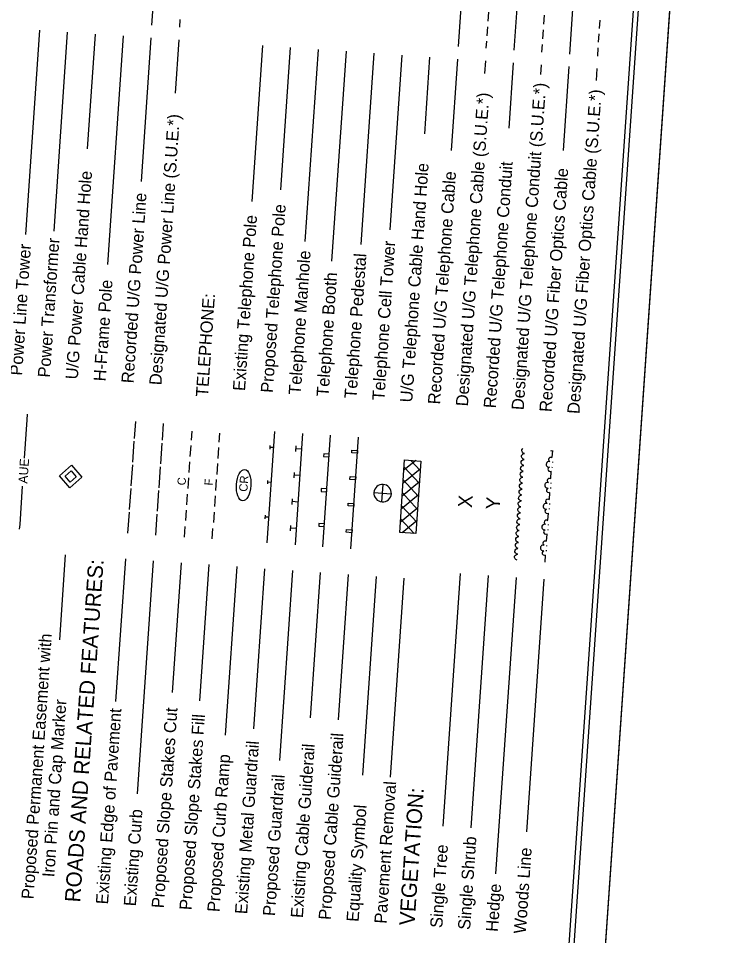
# Model space of a CAD drawing. Extents: x 2598107 to 2605763, y 726018 to 731166.
# Drawn here: x 2604643 to 2605763, y 728143 to 729620 of the extents above; entities that cross this region are included whole.
import ezdxf

# ---------------------------------------------------------------- set-up
doc = ezdxf.new("R2010")
doc.units = 0
for name, color, linetype in [('Prop ROW Permanent Easement CELL', 7, 'Continuous'), ('Prop WCC CELL', 7, 'Continuous'), ('Sheet Cutting Line CELL', 7, 'Continuous'), ('Sheet Plot Border Inside CELL', 7, 'Continuous'), ('Sheet Plot Border Outside CELL', 7, 'Continuous'), ('Sheet Symbology CELL', 7, 'Continuous')]:
    doc.layers.add(name, color=color, linetype=linetype)

msp = doc.modelspace()

# ---------------------------------------------------------------- linework, layer by layer
at = {"layer": 'Prop ROW Permanent Easement CELL'}
msp.add_line((2604727.3, 728882.4), (2604727.3, 728882.4), dxfattribs=at)
for points in [[(2604709.2, 728883.6), (2604728.5, 728900.4), (2604745.3, 728881.1), (2604726, 728864.3)], [(2604718.2, 728883), (2604727.9, 728891.4), (2604736.3, 728881.7), (2604726.6, 728873.3)]]:
    msp.add_lwpolyline(points, close=True, dxfattribs=at)
at = {"layer": 'Prop WCC CELL'}
msp.add_ellipse((2605006, 728868.4), major_axis=(1.7, 25.2), ratio=0.462467, dxfattribs=at)
at = {"layer": 'Sheet Cutting Line CELL'}
msp.add_line((2605502.8, 726876.6), (2605763.1, 730656.7), dxfattribs=at)
at = {"layer": 'Sheet Plot Border Inside CELL'}
msp.add_lwpolyline([(2605454.4, 726909.3), (2605712, 730650.1), (2603343.7, 730813.2), (2603086, 727072.4)], close=True, dxfattribs=at)
at = {"layer": 'Sheet Plot Border Outside CELL'}
msp.add_lwpolyline([(2605502.8, 726876.6), (2605763.1, 730656.7), (2603294, 730826.7), (2603033.6, 727046.7)], close=True, dxfattribs=at)
at = {"layer": 'Sheet Symbology CELL'}
for p, q in [((2604858, 729609), (2604863.9, 729694.5)), ((2605351.8, 729575), (2605357.6, 729658.3)), ((2605441.6, 729568.8), (2605447.4, 729652)), ((2605531.4, 729562.6), (2605537, 729643.1)), ((2605399.8, 729615.7), (2605400.8, 729630.3)), ((2604902.9, 729605.9), (2604903.8, 729618.2)), ((2605489.6, 729610.8), (2605490.6, 729625.4)), ((2605579.4, 729604), (2605580.3, 729617.5)), ((2604677.1, 729601.1), (2604654.4, 729272.3)), ((2604721.9, 729598), (2604699.9, 729277.3)), ((2605398.1, 729592.1), (2605399.1, 729606.7)), ((2605488, 729587.2), (2605489, 729601.8)), ((2604766.8, 729594.9), (2604754.1, 729410.1)), ((2604811.7, 729591.8), (2604786.4, 729223.9)), ((2604856.6, 729588.7), (2604840.7, 729357.6)), ((2604901.5, 729585.7), (2604895.6, 729499.9)), ((2605396.7, 729571.9), (2605397.5, 729583.2)), ((2605577.8, 729581.6), (2605578.8, 729595.1)), ((2605036.2, 729576.4), (2605018.9, 729325.2)), ((2605081.1, 729573.3), (2605065.3, 729344.2)), ((2605126, 729570.2), (2605104.7, 729260.7)), ((2605486.5, 729565.7), (2605487.4, 729578.2)), ((2605576.3, 729559.5), (2605577.2, 729572.6)), ((2605170.9, 729567.1), (2605147.6, 729229.3)), ((2605215.8, 729564), (2605194.6, 729256.1)), ((2605260.7, 729560.9), (2605241.3, 729279.8)), ((2605305.6, 729557.8), (2605297.1, 729434.3)), ((2605350.5, 729554.7), (2605340.3, 729407.6)), ((2605395.3, 729551.6), (2605393.9, 729531.1)), ((2605440.2, 729548.6), (2605433, 729443.2)), ((2605485.1, 729545.5), (2605484, 729529.6)), ((2605530, 729542.4), (2605520.8, 729407.6)), ((2605574.9, 729539.3), (2605573.6, 729520.1)), ((2604657.3, 728973.4), (2604657.9, 728982.7)), ((2604653, 728911.6), (2604657.3, 728973.4)), ((2604830.1, 728943.7), (2604832, 728970.7)), ((2604875, 728940.6), (2604876.9, 728967.6)), ((2604922.2, 728955.1), (2604921.2, 728940.7)), ((2604967.1, 728952), (2604966.1, 728937.6)), ((2605043.8, 728775.3), (2605056.2, 728954.9)), ((2605101, 728951.8), (2605088.7, 728772.2)), ((2605133.6, 728769.1), (2605145.9, 728948.7)), ((2604827.5, 728905.6), (2604829.8, 728939.3)), ((2604872.4, 728902.5), (2604874.7, 728936.2)), ((2605178.5, 728766), (2605190.8, 728945.6)), ((2604920.6, 728932), (2604919.4, 728914.4)), ((2604965.5, 728928.9), (2604964.3, 728911.3)), ((2605048.6, 728926.4), (2605048.9, 728932)), ((2605054.4, 728928.8), (2605048.7, 728929.2)), ((2605090.1, 728922.6), (2605090.7, 728931.6)), ((2605099.3, 728926.5), (2605090.4, 728927.1)), ((2605454.2, 728923.4), (2605454.3, 728925.5)), ((2605455.1, 728921.5), (2605454.2, 728923.4)), ((2605454.3, 728925.5), (2605455.6, 728927.3)), ((2605454.9, 728917.7), (2605456.5, 728918.9)), ((2605456.4, 728920.1), (2605455.1, 728921.5)), ((2605455.6, 728927.3), (2605455.7, 728927.4)), ((2605458.5, 728919.3), (2605456.4, 728920.1)), ((2605456.5, 728918.9), (2605458.4, 728919.2)), ((2605503.2, 728912.8), (2605504, 728924)), ((2604918.8, 728906.1), (2604917.6, 728888.7)), ((2605257.3, 728792.1), (2605265.3, 728909)), ((2605283.2, 728907.8), (2605264.2, 728892.3)), ((2605265.3, 728909), (2605291.6, 728907.2)), ((2605290.5, 728891.8), (2605275.2, 728908.3)), ((2605291.6, 728907.2), (2605283.5, 728790.3)), ((2605452.9, 728904.3), (2605453, 728906.5)), ((2605453.8, 728902.5), (2605452.9, 728904.3)), ((2605453, 728906.5), (2605454.3, 728908.2)), ((2605453.5, 728913.9), (2605453.7, 728916)), ((2605454.4, 728912), (2605453.5, 728913.9)), ((2605453.7, 728916), (2605454.9, 728917.7)), ((2605454.3, 728908.2), (2605455.8, 728909.3)), ((2605455.8, 728910.6), (2605454.4, 728912)), ((2605457.9, 728909.7), (2605455.8, 728910.6)), ((2605455.8, 728909.3), (2605457.7, 728909.6)), ((2605503.8, 728904.8), (2605503.8, 728905.9)), ((2604824.9, 728867.4), (2604827.2, 728901.1)), ((2604869.8, 728864.3), (2604872.1, 728898)), ((2604963.7, 728903), (2604962.5, 728885.6)), ((2605087.2, 728880), (2605087.8, 728888.9)), ((2605290.7, 728894.4), (2605262.7, 728871.4)), ((2605289.1, 728871.1), (2605264.5, 728897.5)), ((2605451.7, 728887.4), (2605452.9, 728889.1)), ((2605452.2, 728894.8), (2605452.4, 728896.9)), ((2605453.1, 728892.9), (2605452.2, 728894.8)), ((2605452.4, 728896.9), (2605453.6, 728898.6)), ((2605452.9, 728889.1), (2605454.5, 728890.2)), ((2605454.5, 728891.5), (2605453.1, 728892.9)), ((2605453.6, 728898.6), (2605455.1, 728899.8)), ((2605455.1, 728901), (2605453.8, 728902.5)), ((2605456.5, 728890.7), (2605454.5, 728891.5)), ((2605454.5, 728890.2), (2605456.4, 728890.6)), ((2605457.2, 728900.2), (2605455.1, 728901)), ((2605455.1, 728899.8), (2605457.1, 728900.1)), ((2605500.9, 728879.2), (2605501.6, 728890.4)), ((2605503.2, 728896.9), (2605503.3, 728898)), ((2604917, 728880.4), (2604915.8, 728862.8)), ((2604961.9, 728877.3), (2604960.7, 728859.8)), ((2605044.7, 728870.3), (2605045.1, 728875.9)), ((2605096.4, 728883.8), (2605087.5, 728884.4)), ((2605287.6, 728850.2), (2605263.1, 728876.7)), ((2605450.9, 728875.7), (2605451, 728877.8)), ((2605451.8, 728873.8), (2605450.9, 728875.7)), ((2605451, 728877.8), (2605452.3, 728879.6)), ((2605451.6, 728885.3), (2605451.7, 728887.4)), ((2605452.4, 728883.4), (2605451.6, 728885.3)), ((2605453.1, 728872.4), (2605451.8, 728873.8)), ((2605452.3, 728879.6), (2605453.8, 728880.7)), ((2605453.8, 728881.9), (2605452.4, 728883.4)), ((2605455.9, 728881.1), (2605453.8, 728881.9)), ((2605453.8, 728880.7), (2605455.8, 728881)), ((2604645.7, 728805), (2604649.9, 728866.7)), ((2604822.2, 728829.3), (2604824.6, 728862.9)), ((2604867.1, 728826.2), (2604869.5, 728859.8)), ((2605050.5, 728872.7), (2605044.9, 728873.1)), ((2605229.8, 728855.5), (2605230.7, 728869.5)), ((2605289.2, 728873.5), (2605261.3, 728850.7)), ((2605449.7, 728858.8), (2605451, 728860.5)), ((2605450.2, 728866.2), (2605450.4, 728868.3)), ((2605451.1, 728864.3), (2605450.2, 728866.2)), ((2605450.4, 728868.3), (2605451.6, 728870)), ((2605451, 728860.5), (2605452.5, 728861.6)), ((2605452.5, 728862.9), (2605451.1, 728864.3)), ((2605451.6, 728870), (2605453.2, 728871.2)), ((2605454.6, 728862), (2605452.5, 728862.9)), ((2605452.5, 728861.6), (2605454.5, 728861.9)), ((2605455.2, 728871.6), (2605453.1, 728872.4)), ((2605453.2, 728871.2), (2605455.1, 728871.5)), ((2605500.9, 728863.2), (2605501, 728864.4)), ((2605501.4, 728871.1), (2605501.5, 728872.2)), ((2604915.2, 728854), (2604914.1, 728836.9)), ((2604960.1, 728850.9), (2604958.9, 728833.8)), ((2605084.3, 728837.3), (2605084.9, 728846.3)), ((2605215.7, 728856.4), (2605229.8, 728855.5)), ((2605228.8, 728841.4), (2605229.8, 728855.5)), ((2605229.8, 728855.5), (2605243.8, 728854.5)), ((2605287.8, 728852.7), (2605259.9, 728829.9)), ((2605286.2, 728829.3), (2605261.6, 728855.9)), ((2605448.9, 728847.1), (2605449.1, 728849.2)), ((2605449.8, 728845.2), (2605448.9, 728847.1)), ((2605449.1, 728849.2), (2605450.3, 728850.9)), ((2605449.6, 728856.6), (2605449.7, 728858.8)), ((2605450.5, 728854.8), (2605449.6, 728856.6)), ((2605451.2, 728843.8), (2605449.8, 728845.2)), ((2605450.3, 728850.9), (2605451.9, 728852.1)), ((2605451.8, 728853.3), (2605450.5, 728854.8)), ((2605453.9, 728852.5), (2605451.8, 728853.3)), ((2605451.9, 728852.1), (2605453.8, 728852.4)), ((2605498.5, 728845.5), (2605499.3, 728856.7)), ((2605093.4, 728841.2), (2605084.6, 728841.8)), ((2605286.4, 728831.9), (2605258.4, 728809)), ((2605284.8, 728808.6), (2605260.2, 728835.1)), ((2605447.6, 728828), (2605447.8, 728830.1)), ((2605447.8, 728830.1), (2605449, 728831.9)), ((2605448.3, 728837.6), (2605448.4, 728839.7)), ((2605449.2, 728835.7), (2605448.3, 728837.6)), ((2605448.4, 728839.7), (2605449.7, 728841.4)), ((2605449, 728831.9), (2605450.5, 728833)), ((2605450.5, 728834.2), (2605449.2, 728835.7)), ((2605449.7, 728841.4), (2605451.2, 728842.5)), ((2605452.6, 728833.4), (2605450.5, 728834.2)), ((2605450.5, 728833), (2605452.5, 728833.3)), ((2605453.3, 728843), (2605451.2, 728843.8)), ((2605451.2, 728842.5), (2605453.1, 728842.9)), ((2605498.6, 728829.6), (2605498.7, 728830.7)), ((2605499.1, 728837.4), (2605499.2, 728838.6)), ((2604819.6, 728791.1), (2604821.9, 728824.8)), ((2604864.5, 728788), (2604866.8, 728821.7)), ((2604913.4, 728828.2), (2604912.3, 728811.2)), ((2604958.3, 728825.1), (2604957.2, 728808.1)), ((2605040.8, 728814.2), (2605041.2, 728819.8)), ((2605046.6, 728816.6), (2605041, 728817)), ((2605447, 728818.5), (2605447.1, 728820.6)), ((2605447.8, 728816.6), (2605447, 728818.5)), ((2605447.1, 728820.6), (2605448.3, 728822.3)), ((2605448.5, 728826.1), (2605447.6, 728828)), ((2605449.2, 728815.2), (2605447.8, 728816.6)), ((2605448.3, 728822.3), (2605449.9, 728823.5)), ((2605449.9, 728824.7), (2605448.5, 728826.1)), ((2605451.3, 728814.3), (2605449.2, 728815.2)), ((2605451.9, 728823.9), (2605449.9, 728824.7)), ((2605449.9, 728823.5), (2605451.8, 728823.8)), ((2605496.2, 728811.8), (2605497, 728823)), ((2604645.1, 728797.5), (2604645.7, 728805)), ((2604910.5, 728784.8), (2604911.6, 728801.9)), ((2605081.3, 728794.7), (2605081.9, 728803.6)), ((2605280.9, 728790.4), (2605258.8, 728814.2)), ((2605284.9, 728811), (2605261.3, 728791.8)), ((2605445.6, 728799.4), (2605445.8, 728801.5)), ((2605445.8, 728801.5), (2605447, 728803.2)), ((2605446.3, 728808.9), (2605446.4, 728811.1)), ((2605447.2, 728807.1), (2605446.3, 728808.9)), ((2605446.4, 728811.1), (2605447.7, 728812.8)), ((2605447, 728803.2), (2605448.6, 728804.4)), ((2605448.5, 728805.6), (2605447.2, 728807.1)), ((2605447.7, 728812.8), (2605449.2, 728813.9)), ((2605450.6, 728804.8), (2605448.5, 728805.6)), ((2605448.6, 728804.4), (2605450.5, 728804.7)), ((2605449.2, 728813.9), (2605451.2, 728814.2)), ((2605496.8, 728803.8), (2605496.9, 728804.9)), ((2604955.4, 728781.8), (2604956.5, 728798.8)), ((2605090.5, 728798.5), (2605081.6, 728799.1)), ((2605258.6, 728792), (2605257.3, 728793.3)), ((2605283.5, 728790.3), (2605257.3, 728792.1)), ((2605445, 728789.9), (2605445.1, 728792)), ((2605445.9, 728788), (2605445, 728789.9)), ((2605445.1, 728792), (2605446.4, 728793.7)), ((2605446.5, 728797.5), (2605445.6, 728799.4)), ((2605445.7, 728784.2), (2605447.3, 728785.3)), ((2605447.2, 728786.5), (2605445.9, 728788)), ((2605446.4, 728793.7), (2605447.9, 728794.8)), ((2605447.9, 728796.1), (2605446.5, 728797.5)), ((2605449.3, 728785.7), (2605447.2, 728786.5)), ((2605447.3, 728785.3), (2605449.2, 728785.6)), ((2605450, 728795.3), (2605447.9, 728796.1)), ((2605447.9, 728794.8), (2605449.9, 728795.2)), ((2605493.9, 728778.1), (2605494.7, 728789.4)), ((2605496.3, 728795.9), (2605496.3, 728797)), ((2605443.7, 728770.8), (2605443.8, 728772.9)), ((2605444.6, 728768.9), (2605443.7, 728770.8)), ((2605443.8, 728772.9), (2605445.1, 728774.6)), ((2605444.3, 728780.3), (2605444.5, 728782.4)), ((2605445.2, 728778.4), (2605444.3, 728780.3)), ((2605444.5, 728782.4), (2605445.7, 728784.2)), ((2605445.1, 728774.6), (2605446.6, 728775.8)), ((2605446.6, 728777), (2605445.2, 728778.4)), ((2605448.7, 728776.2), (2605446.6, 728777)), ((2605446.6, 728775.8), (2605448.5, 728776.1)), ((2605494.5, 728770.1), (2605494.6, 728771.2)), ((2604718.6, 728756.3), (2604709.1, 728619.3)), ((2605443, 728761.2), (2605443.2, 728763.4)), ((2605443.9, 728759.4), (2605443, 728761.2)), ((2605443.2, 728763.4), (2605444.4, 728765.1)), ((2605443.7, 728755.5), (2605445.3, 728756.7)), ((2605445.3, 728757.9), (2605443.9, 728759.4)), ((2605444.4, 728765.1), (2605445.9, 728766.2)), ((2605445.9, 728767.5), (2605444.6, 728768.9)), ((2605447.4, 728757.1), (2605445.3, 728757.9)), ((2605445.3, 728756.7), (2605447.2, 728757)), ((2605448, 728766.6), (2605445.9, 728767.5)), ((2605445.9, 728766.2), (2605447.9, 728766.5)), ((2605491.6, 728744.5), (2605492.4, 728755.7)), ((2605493.9, 728762.2), (2605494, 728763.4)), ((2604815.5, 728749.6), (2604799.6, 728519.9)), ((2604860.3, 728746.5), (2604834.5, 728371.3)), ((2604905.2, 728743.4), (2604890.8, 728534.2)), ((2605442.4, 728751.7), (2605442.5, 728753.8)), ((2605443.2, 728749.8), (2605442.4, 728751.7)), ((2605442.5, 728753.8), (2605443.7, 728755.5)), ((2605444.6, 728748.4), (2605443.2, 728749.8)), ((2605446.7, 728747.6), (2605444.6, 728748.4)), ((2604950.1, 728740.3), (2604935, 728520.9)), ((2604995, 728737.2), (2604976.3, 728465.8)), ((2605039.6, 728733.8), (2605021.9, 728476)), ((2605084.5, 728730.7), (2605063.5, 728424.9)), ((2605129.4, 728727.6), (2605113.3, 728493.5)), ((2605174.3, 728724.5), (2605158.2, 728490.4)), ((2605219.2, 728721.4), (2605197.2, 728401.3)), ((2605264.1, 728718.3), (2605242, 728398.2)), ((2605355, 728725.9), (2605327, 728319.4)), ((2605399.9, 728722.8), (2605371.9, 728316.3)), ((2605444.8, 728719.7), (2605411.9, 728242.3)), ((2605489.7, 728716.7), (2605461.7, 728310.1))]:
    msp.add_line(p, q, dxfattribs=at)
for points in [[(2603347.4, 730784.7), (2603115.6, 727417.7), (2605470.2, 727255.5), (2605702.1, 730622.6)], [(2605143.5, 728913.9), (2605143.8, 728918.3), (2605134.9, 728919), (2605134.6, 728914.5)], [(2605180.1, 728920.3), (2605180.4, 728924.8), (2605189.4, 728924.2), (2605189.1, 728919.7)], [(2605177.1, 728877.7), (2605177.4, 728882.2), (2605186.4, 728881.6), (2605186.1, 728877.1)], [(2605139.7, 728857.7), (2605140, 728862.2), (2605131, 728862.8), (2605130.7, 728858.4)], [(2605174.2, 728835), (2605174.5, 728839.5), (2605183.5, 728838.9), (2605183.2, 728834.4)], [(2605135.8, 728801.6), (2605136.1, 728806.1), (2605127.1, 728806.7), (2605126.8, 728802.2)], [(2605171.3, 728792.4), (2605171.6, 728796.9), (2605180.5, 728796.3), (2605180.2, 728791.8)]]:
    msp.add_lwpolyline(points, close=True, dxfattribs=at)
for centre, radius, start, end in [((2605501.9, 728927.4), 3.56, 242.3111, 289.8091), ((2605497.9, 728901.8), 4.64, 72.0239, 280.0963), ((2605500.7, 728909.5), 3.56, 46.8286, 247.6252), ((2605499.6, 728893.8), 3.56, 104.4951, 305.2916), ((2605498.3, 728875.8), 3.56, 46.8286, 247.6252), ((2605229.8, 728855.5), 14.1, 86.0545, 176.059), ((2605229.8, 728855.5), 14.1, 356.0545, 86.059), ((2605495.6, 728868.1), 4.64, 72.0239, 280.0963), ((2605497.3, 728860.1), 3.56, 104.4951, 305.2916), ((2605229.8, 728855.5), 14.1, 176.0545, 266.059), ((2605229.8, 728855.5), 14.1, 266.0545, 356.059), ((2605496, 728842.2), 3.56, 46.8286, 247.6252), ((2605493.2, 728834.4), 4.64, 72.0239, 280.0963), ((2605494.9, 728826.4), 3.56, 104.4951, 305.2916), ((2605490.9, 728800.8), 4.64, 72.0239, 280.0963), ((2605493.7, 728808.5), 3.56, 46.8286, 247.6252), ((2605492.6, 728792.8), 3.56, 104.4951, 305.2916), ((2605488.6, 728767.1), 4.64, 72.0239, 280.0963), ((2605491.4, 728774.8), 3.56, 46.8286, 247.6252), ((2605490.3, 728759.1), 3.56, 104.4951, 305.2916)]:
    msp.add_arc(centre, radius, start, end, dxfattribs=at)

# ---------------------------------------------------------------- texts
at = {"layer": 'Prop WCC CELL'}
msp.add_text('CR', height=13.5, rotation=86.0601, dxfattribs=at).set_placement((2605011.9, 728857.4))
at = {"layer": 'Sheet Symbology CELL'}
for s, height, p in [('Designated U/G Telephone Conduit (S.U.E.*)', 19.688, (2605457, 728988.8)), ('Designated U/G Telephone Cable (S.U.E.*)', 19.688, (2605367.2, 728994.9)), ('Designated U/G Fiber Optics Cable (S.U.E.*)', 19.688, (2605546.8, 728982.6)), ('Designated U/G Power Line (S.U.E.*)', 19.688, (2604873.4, 729028.9)), ('U/G Telephone Cable Hand Hole', 19.688, (2605277.5, 729001.1)), ('Recorded U/G Telephone Conduit', 19.688, (2605412.1, 728991.8)), ('Recorded U/G Fiber Optics Cable', 19.688, (2605501.9, 728985.7)), ('U/G Power Cable Hand Hole', 19.688, (2604738.7, 729038.2)), ('Recorded U/G Telephone Cable', 19.688, (2605322.3, 728998)), ('Recorded U/G Power Line', 19.688, (2604828.5, 729032)), ('Proposed Telephone Pole', 19.688, (2605053, 729016.6)), ('Existing Telephone Pole', 19.688, (2605008.1, 729019.6)), ('Power Transformer', 19.688, (2604693.8, 729041.2)), ('Telephone Cell Tower', 19.688, (2605232.6, 729004.2)), ('Power Line Tower', 19.688, (2604648.9, 729044.4)), ('Telephone Manhole', 19.688, (2605097.9, 729013.5)), ('Telephone Pedestal', 19.688, (2605187.7, 729007.3)), ('Telephone Booth', 19.688, (2605142.8, 729010.4)), ('H-Frame Pole', 19.688, (2604783.6, 729035.1)), ('TELEPHONE:', 19.69, (2604948.4, 729010.1)), ('AUE', 14.74, (2604657.6, 728870.5)), ('C', 13.3, (2604912.3, 728867.7)), ('F', 13.3, (2604955.9, 728867.4)), ('X', 22.5, (2605373.5, 728831.5)), ('Y', 22.5, (2605418.4, 728828.4)), ('ROADS AND RELATED FEATURES:', 24.75, (2604742.5, 728195.9)), ('Proposed Permanent Easement with', 19.688, (2604667.5, 728201)), ('Iron Pin and Cap Marker', 19.688, (2604700.9, 728236.5)), ('Existing Edge of Pavement', 19.688, (2604787.4, 728192.8)), ('Proposed Slope Stakes Cut', 19.688, (2604877.2, 728186.6)), ('Proposed Slope Stakes Fill', 19.688, (2604922, 728183.5)), ('Proposed Cable Guiderail', 19.688, (2605146.2, 728167.7)), ('Existing Metal Guardrail', 19.688, (2605011.5, 728177)), ('Existing Cable Guiderail', 19.688, (2605101.3, 728170.8)), ('Proposed Curb Ramp', 19.688, (2604966.9, 728180.4)), ('Proposed Guardrail', 19.688, (2605056.4, 728173.9)), ('Pavement Removal', 19.688, (2605236, 728161.6)), ('VEGETATION:', 24.75, (2605281.1, 728158.4)), ('Existing Curb', 19.688, (2604832.3, 728189.7)), ('Equality Symbol', 19.688, (2605191.1, 728164.6)), ('Single Shrub', 19.688, (2605370.7, 728151.6)), ('Single Tree', 19.688, (2605325.9, 728154.7)), ('Woods Line', 19.69, (2605460.5, 728145.4)), ('Hedge', 19.69, (2605415.6, 728148.5))]:
    msp.add_text(s, height=height, rotation=86.0601, dxfattribs=at).set_placement(p)

doc.saveas('drawing.dxf')
